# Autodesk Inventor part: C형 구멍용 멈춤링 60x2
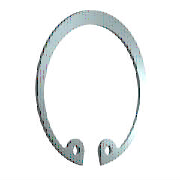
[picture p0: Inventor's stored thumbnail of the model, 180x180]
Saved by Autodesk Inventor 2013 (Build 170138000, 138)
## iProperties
IsCustomPart: 1
Created: 2012-02
Part Number: C형 구멍용 멈춤링 60x2
Material: 강철, 연강
Description: 스프링 리테이닝 링
Document SubType Name: Modeling
Standard: JIS B 2804
Designer: mdu-01
Standards Organization: JIS
Language: ko-KR
Size Designation: 60x2
Categories: <MemberInstance><Categories><Category DisplayName="샤프트 부품" InternalName="7f7aeb1f-a693-4053-b835-cee3144e0d98" Mnemonic="SHFT"><Category DisplayName="써클립" Inter
Density: 1 g/cm^3
Author: mdu-01
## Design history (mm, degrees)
sketch "스케치1"
  geometry: L1 (0, 15.113)-(0, -73.177) reference; L2 (-45.5, 0)-(45.5, 0) reference; L3 (-4.964, 1.5)-(1.502, 1.5); L4 (0, -4)-(-5.307, -4); L5 (0, -30)-(-13.027, -58.68); L6 (-13.027, -58.68)-(-26.582, -52.523); L7 (-11.621, -55.584)-(-22.16, -50.797); L8 (-9.345, -56.618)-(-10.71, -59.623); L9 (9.345, -56.618)-(10.71, -59.623); C1 r 1.25 at (-11.621, -55.584); C2 r 1.25 at (11.621, -55.584); A1 r 27.375 centre (0, -31.375) between (16.027, -53.568) and (-16.027, -53.568); A2 r 31.5 centre (0, -30) between (10.71, -59.623) and (-10.71, -59.623); A3 r 2.5 centre (-11.621, -55.584) between (-9.345, -56.618) and (-13.092, -53.563); A4 r 2.5 centre (-14.563, -51.541) between (-16.027, -53.568) and (-13.092, -53.563); A5 r 2.5 centre (14.563, -51.541) between (13.092, -53.563) and (16.027, -53.568); A6 r 2.5 centre (11.621, -55.584) between (13.092, -53.563) and (9.345, -56.618); 3 further points
  constraints: 15 point on circle, 14 end point, 9 symmetric about line, 8 centre point, 6 tangent, 4 coincident, 4 point on line, 3 perpendicular, 1 parallel, 4 other
  dimensions: "d8" = 1.375 distance of A1.centre L5.start (= 0.25 x SRB1); "d38" = 5.5 distance between parallel lines of L4 L3 (= SRB1); "d39" = 30 distance from line of L5.start L2 (= 0.5 x WD); "d43" = 31.5 radius of A2 (= 0.5 x ND); "d45" = 3.4 distance between parallel lines of L7 L6 (= 0.5 x SRB2); "d46" = 2.5 radius of A4 (= SD5); "d47" = 10.71 distance from line of L1 L8.end (= 0.17 x ND); "d48" = 2.5 diameter of C1 (= SD5); "d49" = 2.5 radius of A3 (= SD5)
extrude "본체" new body sketch "스케치1" distance "d2" = 2 (= SD); taper "d3" = 0 deg
workaxis "Work Axis1"
workaxis "Work Axis2"
workplane "Work Plane1"
body "Solid1"
other parameters: "SD" = 2 [user parameter; used in 1 equation term], "SRB1" = 5.5 [user parameter; used in 2 equation terms], "ND" = 63 [user parameter; used in 2 equation terms], "SRB2" = 6.8 [user parameter; used in 1 equation term], "SD5" = 2.5 [user parameter; used in 3 equation terms], "d50" = 0, "d51" = 0, "d52" = 0, "d53" = 0, "WDMIN" = 58 [user parameter], "SD6" = 64.2 [user parameter]
